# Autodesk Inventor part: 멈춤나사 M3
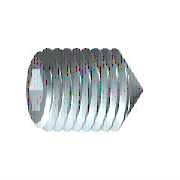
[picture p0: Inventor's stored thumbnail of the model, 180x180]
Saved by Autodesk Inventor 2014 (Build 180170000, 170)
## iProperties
IsCustomPart: 1
Created: 2012-02
Part Number: 멈춤나사 M3
Material: 강철, 연강
Description: 6각 소켓 머리 없는 멈춤 나사
Document SubType Name: Modeling
Standard: KS B 1028
Designer: test
Standards Organization: KS
Language: ko-KR
Size Designation: 원추점 M3x8
Categories: <MemberInstance><Categories><Category DisplayName="조임쇠" InternalName="e4da775c-781d-43d5-af7c-5136215cf5a6" Mnemonic="FSTN"><Category DisplayName="볼트" InternalN
Density: 1 g/cm^3
Appearance: Steel
Author: test
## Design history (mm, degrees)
sketch "스케치1"
  geometry: L1 (0, 0)-(5.5, 0); L2 (8, 0.866)-(8, 1.5); L3 (8, 1.5)-(0, 1.5); L4 (8, 0.866)-(6, 0.866); L5 (6, 0.866)-(5.5, 0); L6 (0, -0.3)-(0, 1.8) reference; L7 (0, 1.5)-(0, 0)
  constraints: 13 end point, 3 parallel, 1 collinear, 1 perpendicular, 1 point on line
  dimensions: "d0" = 2 distance of L2.start L4.end (= INTI); "d1" = 60 deg angle of L5 L1; "d2" = 3 diameter of L3 L1 (= NND); "d3" = 1.73205 diameter of L4 L1 (= 1.1547 x SW); "d5" = 8 distance from line of L2 L3.end (= NLG)
revolve "본체" sketch "스케치1" stored, may be unused: angle "d6" = 90 deg
sketch "스케치2"
  geometry: L1 (-0.433, 0.75)-(0.433, 0.75); L2 (0.433, 0.75)-(0.866, 0); L3 (0.866, 0)-(0.433, -0.75); L4 (0.433, -0.75)-(-0.433, -0.75); L5 (-0.433, -0.75)-(-0.866, 0); L6 (-0.866, 0)-(-0.433, 0.75); 3 further points
  constraints: 12 end point, 1 coincident, 1 horizontal, 13 other
extrude "슬롯" join sketch "스케치2" taper "d7" = 0 deg; stored distance "d21" = 10
workaxis "Work Axis1"
workplane "Work Plane1"
sketch "스케치4"
  geometry: L1 (0, 0.15)-(-1.35, 1.5) reference; L2 (0, -0.15)-(-1.35, -1.5) reference; L3 (-1.35, -1.5)-(0.15, 0); L4 (-1.35, 1.5)-(0.15, 0); 2 further points
  constraints: 4 end point, 1 coincident, 1 collinear, 1 horizontal alignment
workpoint "Work Point1"
  workaxis "Work Axis2"
body "Solid1"
feature "스레드" dims "d12" = 8 (= NLG), "d13" = 0
chamfer "모따기1" distance "d8" = 1.35 (computed from NND, SPD, FAWI); stored, may be unused: angle "d9" = 45 deg (= FAWI), second distance "d34" = 1.35 (computed from NND, SPD, FAWI)
chamfer "모따기2" distance "d10" = 0.30673 (= -0.5 x GD1 + 0.5 x NND); stored, may be unused: angle "d11" = 45 deg (= FAWI), second distance "d35" = 0.30673 (= -0.5 x GD1 + 0.5 x NND)
other parameters: "NND" = 3 [user parameter; used in 5 equation terms], "NLG" = 8 [user parameter; used in 2 equation terms], "INTI" = 2 [user parameter; used in 1 equation term], "FAWI" = 45 deg [user parameter; used in 4 equation terms], "SW" = 1.5 [user parameter; used in 2 equation terms], "GD1" = 2.38655 (= THREADDIA - 1.2269 x PTC) [user parameter; used in 2 equation terms], "d4" = 0, "FAWI1" = 45 deg [user parameter], "SPD" = 0.3 [user parameter; used in 2 equation terms], "d36" = 0, "d37" = 0, "GUL" = 0.30673 (= 0.61345 x PTC) [user parameter], "TOA" = 30 deg [user parameter], "THREADDIA" = 3 [user parameter; used in 1 equation term], "PTC" = 0.5 [user parameter; used in 4 equation terms], "GAL" = 0.30673 (= 0.61345 x PTC) [user parameter], "E0" = 1.7325 (= 1.155 x SW) [user parameter]
